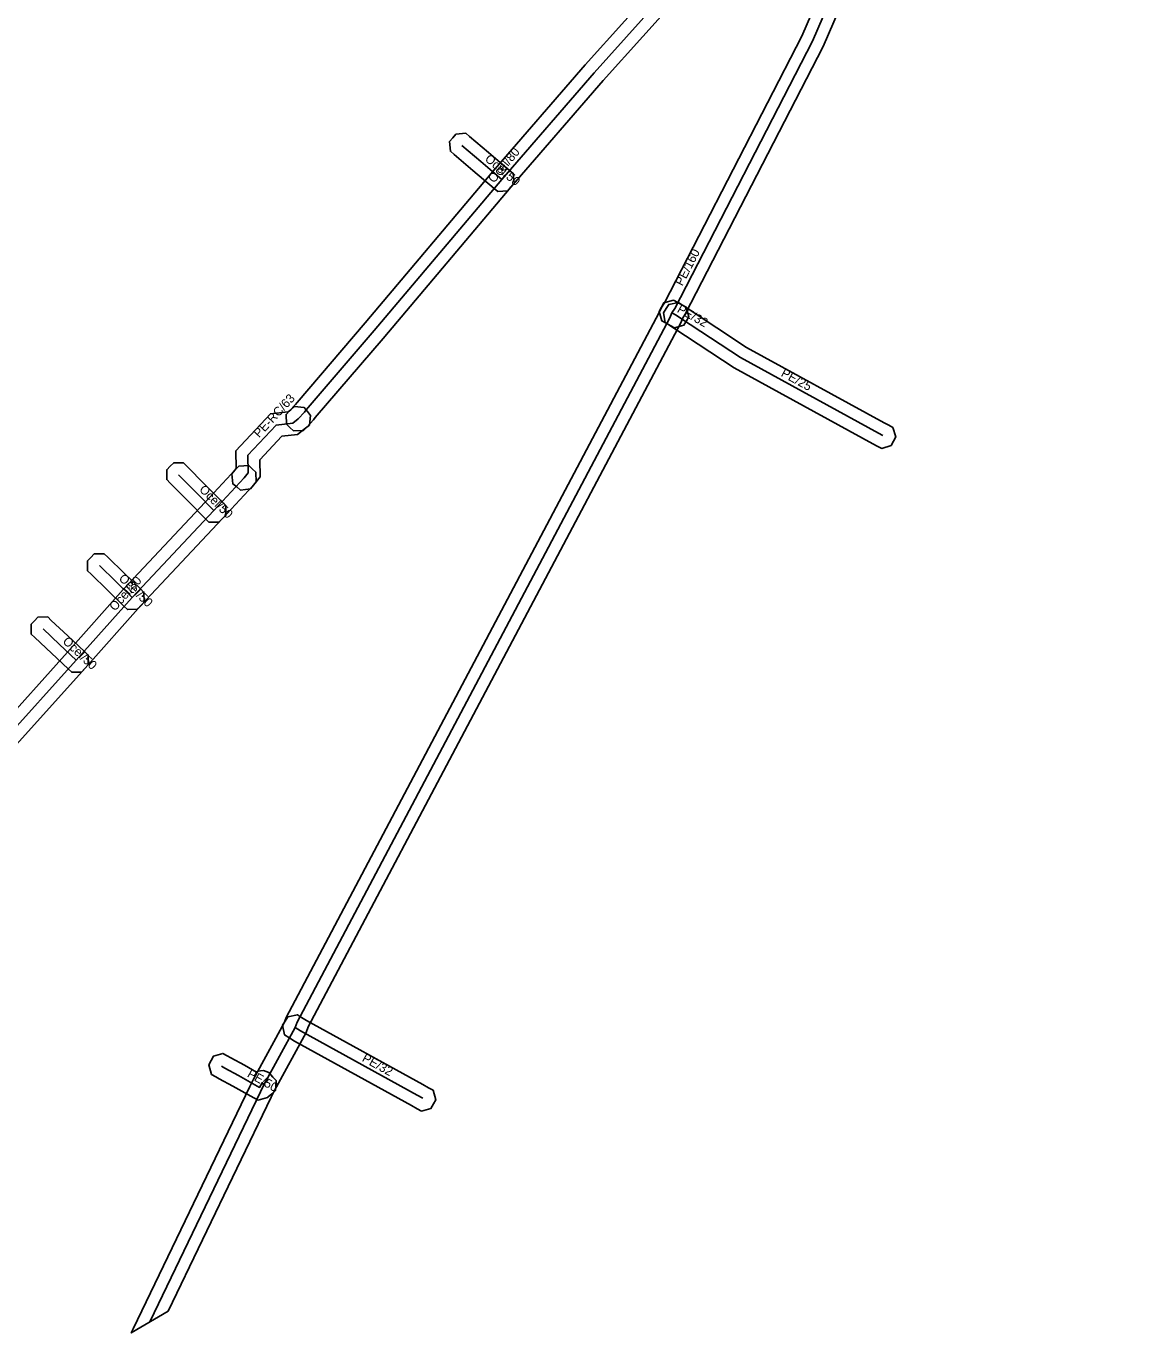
# Model space of a CAD drawing. Extents: x -843502 to -843208, y -997248 to -997028.
# Drawn here: x -843367.1 to -843272.5, y -997248.3 to -997138.4 of the extents above; entities that cross this region are included whole.
import ezdxf

# ---------------------------------------------------------------- set-up
doc = ezdxf.new("R2010")
doc.units = 0
for name, color, linetype in [('1', 7, 'Continuous'), ('24', 7, 'Continuous'), ('30', 7, 'Continuous')]:
    doc.layers.add(name, color=color, linetype=linetype)

msp = doc.modelspace()

# ---------------------------------------------------------------- linework, layer by layer
at = {"layer": '1'}
for points in [[(-843287.9, -997112.07), (-843300.02, -997140.1), (-843311.64, -997162.64), (-843311.85, -997162.98), (-843312, -997163.36), (-843343.35, -997222.58), (-843343.51, -997223.04), (-843346.18, -997227.92), (-843346.46, -997228.48), (-843355.12, -997246.48), (-843358.23, -997248.31), (-843358.06, -997247.97), (-843348.26, -997227.58), (-843347.94, -997226.98), (-843345.35, -997222.22), (-843345.19, -997221.78), (-843313.82, -997162.5), (-843313.63, -997162.06), (-843313.38, -997161.66), (-843301.82, -997139.24), (-843289.74, -997111.29)], [(-843311.84, -997135.53), (-843318.54, -997142.98), (-843326.29, -997151.94), (-843337.04, -997164.66), (-843342.74, -997171.32), (-843342.9, -997171.52), (-843343.46, -997172.12), (-843343.74, -997172.42), (-843344.57, -997172.45), (-843344.87, -997172.17), (-843345.17, -997171.89), (-843345.2, -997171.06), (-843344.92, -997170.76), (-843344.42, -997170.22), (-843344.28, -997170.05), (-843338.56, -997163.36), (-843327.81, -997150.64), (-843320.04, -997141.66), (-843313.36, -997134.23)], [(-843369.6, -997197.74), (-843363.59, -997191.07), (-843358.89, -997185.79), (-843352, -997178.45), (-843349.45, -997175.7), (-843349.17, -997175.4), (-843348.34, -997175.36), (-843348.04, -997175.65), (-843347.74, -997175.93), (-843347.71, -997176.76), (-843347.99, -997177.06), (-843350.54, -997179.81), (-843357.41, -997187.14), (-843362.1, -997192.41), (-843368.37, -997199.37)]]:
    msp.add_lwpolyline(points, dxfattribs=at)
for points in [[(-843330.09, -997147.41), (-843329.77, -997147.68), (-843328.18, -997149.03), (-843326.41, -997150.53), (-843326.09, -997150.79), (-843326.02, -997151.62), (-843326.29, -997151.93), (-843326.55, -997152.25), (-843327.38, -997152.32), (-843327.69, -997152.06), (-843329.48, -997150.55), (-843331.07, -997149.2), (-843331.38, -997148.93), (-843331.45, -997148.11), (-843331.18, -997147.79), (-843330.91, -997147.48)], [(-843312.61, -997161.45), (-843312.25, -997161.65), (-843311.91, -997161.84), (-843311.55, -997162.04), (-843311.33, -997162.84), (-843311.53, -997163.2), (-843311.73, -997163.56), (-843312.53, -997163.79), (-843312.89, -997163.58), (-843313.23, -997163.39), (-843313.59, -997163.19), (-843313.82, -997162.39), (-843313.61, -997162.03), (-843313.41, -997161.67)], [(-843312.2, -997161.65), (-843311.85, -997161.88), (-843311.47, -997162.12), (-843306.46, -997165.42), (-843294.88, -997171.76), (-843294.51, -997171.96), (-843294.15, -997172.16), (-843293.91, -997172.95), (-843294.11, -997173.32), (-843294.31, -997173.68), (-843295.1, -997173.92), (-843295.47, -997173.72), (-843295.84, -997173.52), (-843307.5, -997167.14), (-843312.57, -997163.8), (-843312.95, -997163.55), (-843313.3, -997163.32), (-843313.46, -997162.51), (-843313.23, -997162.16), (-843313.01, -997161.81)], [(-843343.24, -997171.96), (-843343.57, -997172.22), (-843344.23, -997172.75), (-843345.56, -997172.9), (-843347.4, -997174.88), (-843347.37, -997176.31), (-843347.94, -997177.01), (-843348.2, -997177.33), (-843349.03, -997177.42), (-843349.35, -997177.16), (-843349.67, -997176.9), (-843349.76, -997176.07), (-843349.5, -997175.75), (-843349.39, -997175.61), (-843349.42, -997174.12), (-843346.52, -997171), (-843345.03, -997170.83), (-843344.81, -997170.66), (-843344.49, -997170.4), (-843343.67, -997170.49), (-843343.41, -997170.82), (-843343.15, -997171.14)], [(-843353.82, -997175.13), (-843353.53, -997175.43), (-843352.05, -997176.93), (-843350.56, -997178.43), (-843350.27, -997178.72), (-843350.27, -997179.55), (-843350.57, -997179.84), (-843350.86, -997180.13), (-843351.69, -997180.13), (-843351.98, -997179.83), (-843353.47, -997178.33), (-843354.95, -997176.83), (-843355.24, -997176.54), (-843355.24, -997175.71), (-843354.94, -997175.42), (-843354.65, -997175.13)], [(-843360.5, -997182.78), (-843360.2, -997183.07), (-843358.83, -997184.4), (-843357.45, -997185.74), (-843357.16, -997186.03), (-843357.14, -997186.86), (-843357.43, -997187.16), (-843357.72, -997187.45), (-843358.55, -997187.47), (-843358.85, -997187.18), (-843360.23, -997185.84), (-843361.6, -997184.49), (-843361.9, -997184.21), (-843361.91, -997183.38), (-843361.61, -997183.08), (-843361.33, -997182.79)], [(-843365.25, -997188.09), (-843364.95, -997188.38), (-843363.56, -997189.69), (-843362.16, -997191.01), (-843361.86, -997191.3), (-843361.84, -997192.12), (-843362.12, -997192.43), (-843362.41, -997192.73), (-843363.23, -997192.75), (-843363.54, -997192.47), (-843364.94, -997191.15), (-843366.33, -997189.83), (-843366.63, -997189.54), (-843366.65, -997188.71), (-843366.36, -997188.41), (-843366.08, -997188.11)], [(-843333.81, -997229.66), (-843334.17, -997229.46), (-843334.66, -997229.19), (-843344.5, -997223.77), (-843344.97, -997223.47), (-843345.32, -997223.25), (-843345.5, -997222.44), (-843345.27, -997222.09), (-843345.05, -997221.74), (-843344.24, -997221.56), (-843343.89, -997221.79), (-843343.48, -997222.05), (-843333.7, -997227.43), (-843333.21, -997227.7), (-843332.84, -997227.9), (-843332.61, -997228.7), (-843332.81, -997229.06), (-843333.01, -997229.43)], [(-843348.71, -997225.79), (-843347.68, -997226.37), (-843347.58, -997226.31), (-843347.34, -997226.28), (-843347.09, -997226.25), (-843346.64, -997226.42), (-843346.47, -997226.61), (-843346.31, -997226.79), (-843346.04, -997227.09), (-843346.09, -997227.92), (-843346.4, -997228.2), (-843346.71, -997228.47), (-843346.73, -997228.47), (-843346.75, -997228.5), (-843347.15, -997228.62), (-843347.56, -997228.74), (-843347.92, -997228.53), (-843349.67, -997227.55), (-843350.82, -997226.93), (-843351.11, -997226.77), (-843351.48, -997226.57), (-843351.71, -997225.77), (-843351.51, -997225.41), (-843351.31, -997225.04), (-843350.51, -997224.81), (-843350.15, -997225.01), (-843349.86, -997225.17)]]:
    msp.add_lwpolyline(points, close=True, dxfattribs=at)
at = {"layer": '24'}
for points in [[(-843272.54, -997070.78), (-843272.87, -997071.65), (-843287.39, -997108), (-843288.18, -997110.17), (-843288.82, -997111.68), (-843300.92, -997139.67), (-843312.51, -997162.15), (-843312.74, -997162.52), (-843312.91, -997162.93), (-843344.27, -997222.18), (-843344.43, -997222.63), (-843347.06, -997227.45), (-843347.36, -997228.03), (-843356.67, -997247.39)], [(-843310.55, -997132.98), (-843311, -997132.71), (-843311.9, -997134.07), (-843311.94, -997134.12), (-843312.29, -997134.49), (-843312.6, -997134.88), (-843319.29, -997142.32), (-843327.05, -997151.29), (-843337.8, -997164.01), (-843343.51, -997170.68), (-843343.66, -997170.87), (-843344.19, -997171.44)], [(-843330.42, -997148.44), (-843328.83, -997149.79), (-843327.05, -997151.29)], [(-843312.74, -997162.52), (-843312.4, -997162.71)], [(-843312.4, -997162.71), (-843312.02, -997162.96), (-843306.98, -997166.28), (-843295.36, -997172.64), (-843294.99, -997172.84)], [(-843344.19, -997171.44), (-843344.63, -997171.79), (-843346.04, -997171.95), (-843348.41, -997174.5), (-843348.38, -997175.96), (-843348.72, -997176.38)], [(-843369.99, -997199.09), (-843369.64, -997198.74), (-843369.37, -997198.95), (-843369.3, -997198.88), (-843369.1, -997198.68), (-843362.85, -997191.74), (-843358.15, -997186.46), (-843351.27, -997179.13), (-843348.72, -997176.38)], [(-843354.24, -997176.13), (-843352.76, -997177.63), (-843351.27, -997179.13)], [(-843360.9, -997183.78), (-843359.53, -997185.12), (-843358.15, -997186.46)], [(-843365.64, -997189.1), (-843364.25, -997190.42), (-843362.85, -997191.74)], [(-843333.69, -997228.58), (-843334.18, -997228.31), (-843343.99, -997222.91), (-843344.43, -997222.63)], [(-843347.06, -997227.45), (-843347.22, -997227.27), (-843347.43, -997227.66), (-843349.19, -997226.67), (-843350.34, -997226.05), (-843350.63, -997225.89)]]:
    msp.add_lwpolyline(points, dxfattribs=at)

# ---------------------------------------------------------------- texts
at = {"layer": '30'}
for s, rotation, p in [('Ocel/50', 319.8793, (-843328.54, -997149.67)), ('Ocel/80', 49.798, (-843327.72, -997151.65)), ('PE/160', 62.7258, (-843311.87, -997160.31)), ('PE/32', 330.8025, (-843312.37, -997162.42)), ('PE/25', 331.3067, (-843303.63, -997167.8)), ('PE-RC/63', 47.0953, (-843347.47, -997173.07)), ('Ocel/50', 314.8084, (-843352.56, -997177.43)), ('Ocel/80', 48.3261, (-843359.59, -997187.65)), ('Ocel/50', 315.8425, (-843359.33, -997184.92)), ('Ocel/50', 316.6847, (-843364.05, -997190.22)), ('PE/32', 331.169, (-843338.87, -997225.42)), ('PE/50', 330.6422, (-843348.53, -997226.73))]:
    msp.add_text(s, height=0.75, rotation=rotation, dxfattribs=at).set_placement(p)

doc.saveas('drawing.dxf')
